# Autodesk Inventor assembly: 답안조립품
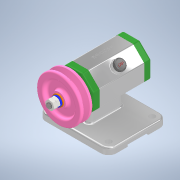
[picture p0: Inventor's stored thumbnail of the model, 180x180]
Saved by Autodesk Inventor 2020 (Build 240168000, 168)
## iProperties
Created: 2022-10
Part Number: 답안조립품
Document SubType Name: Assembly
Designer: 101-13
Author: 101-13
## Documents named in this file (16)
- C:\Users\101-13\Desktop\721006V1012\답안조립품.iam
- C:\Users\101-13\Desktop\721006V1012\본체.ipt
- C:\Users\101-13\Desktop\721006V1012\축.ipt
- C:\Users\101-13\Desktop\721006V1012\베어링 6002.ipt
- C:\Users\101-13\Desktop\721006V1012\뒤커버.ipt
- C:\Users\101-13\Desktop\721006V1012\앞커버.ipt
- C:\Users\101-13\Desktop\721006V1012\오일 실 15x25x7.ipt
- C:\Users\101-13\Desktop\721006V1012\키 3x3x12.ipt
- 키 3x3x12.ipt
- C:\Users\101-13\Desktop\721006V1012\V벨트풀리.ipt
- C:\Users\101-13\Desktop\721006V1012\와셔 8x17.ipt
- C:\Users\101-13\Desktop\721006V1012\스프링와셔 8.ipt
- C:\Users\101-13\Desktop\721006V1012\너트 M8.ipt
- 너트 M8.ipt
- C:\Users\101-13\Desktop\721006V1012\고무캡.ipt
- C:\Users\101-13\Desktop\721006V1012\볼트 M4x12.ipt
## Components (2 placed, 2 different names)
1. V벨트풀리:1 — 각도:1
2. 고무캡:1
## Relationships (1: Angle 1)
- 각도:1 [Angle]: V벨트풀리:1
